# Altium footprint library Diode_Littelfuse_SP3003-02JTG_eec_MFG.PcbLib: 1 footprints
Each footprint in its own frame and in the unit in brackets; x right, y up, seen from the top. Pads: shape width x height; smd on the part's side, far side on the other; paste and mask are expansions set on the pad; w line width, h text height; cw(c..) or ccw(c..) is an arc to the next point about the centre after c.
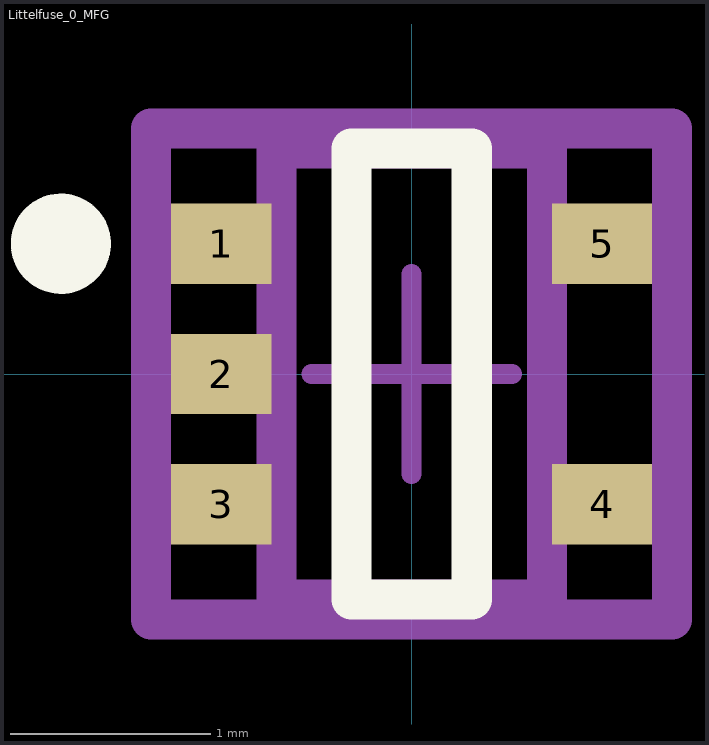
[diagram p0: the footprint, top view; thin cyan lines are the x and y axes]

## Littelfuse_0_MFG [mm]
pads (5):
  rect 0.5x0.4 smd paste+0 mask+0: 1(-0.95,0.65) 2(-0.95,0) 3(-0.95,-0.65) 4(0.95,-0.65) 5(0.95,0.65)
Top Overlay:
  circle w0.25: c-1.75,0.65 r0.125
  lines w0.2: -0.3,-1.125 0.3,-1.125 0.3,1.125 -0.3,1.125 -0.3,-1.125
Mechanical 10:
  lines w0.2: -1.3,-1.225 1.3,-1.225 1.3,1.225 -1.3,1.225 -1.3,-1.225
  text ".Designator" at 0,0 h1
Mechanical 12:
  lines w0.2: -0.675,-1.125 0.675,-1.125 0.675,1.125 -0.675,1.125 -0.675,-1.125
Mechanical 15:
  lines w0.1: -0.5,0 0.5,0 ; 0,-0.5 0,0.5
  lines w0.2: -1.3,-1.225 1.3,-1.225 1.3,1.225 -1.3,1.225 -1.3,-1.225
3D body "Diode_Littelfuse_SP3003-02JTG_eec.STEP": height 0.25, standoff 0, extent -1.3,-1.225 1.3,1.225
